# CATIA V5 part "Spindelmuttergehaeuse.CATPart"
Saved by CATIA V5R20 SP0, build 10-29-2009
Part number: Spindelmuttergehäuse
Bounding box of the stored display mesh (mm): x -38 to 25, y -20 to 20, z 0 to 32
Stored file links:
  C:\Users\Andi\Desktop\Offene Projekte\Plasmacutter\Portal\Spindelmuttergehaeuse.CATPart
  C:\Program Files\Dassault Systemes\B20\win_b64\reffiles\standard\MetricThickPitch.txt
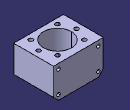
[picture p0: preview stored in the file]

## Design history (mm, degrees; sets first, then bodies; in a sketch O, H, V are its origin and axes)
Body1 (main body)
  Sketch1 on xy-plane, origin (0, 0, 0), H (1, 0, 0), V (0, 1, 0)
    point P1 (0, 0)
    line L1 (25, 20) -> (25, -20)
    line L2 (25, -20) -> (-25, -20)
    line L3 (-25, -20) -> (-25, 20)
    line L4 (-25, 20) -> (25, 20)
    circle A1 centre (0, -1) radius 14
    point P6 (0, -1)
    distance L2 L4 = 40
    distance L1 L3 = 50
    radius A1 = 14
    distance P6 L4 = 21
    coincidence: P1 V, P1 O, P6 V
    vertical: L1 V, L3 V
    horizontal: L2 H, L4 H
    equidistance: L1 L3 P1, L2 L4 P1
  Pad1: profile Sketch1, direction (0, 0, 1), length 32
  Sketch2 on end face of Pad1, origin (-15.5839, 12.1937, 32), H (1, 0, 0), V (0, 1, 0)
    point P1 (-3.4161, -13.1937)
    reference intersected line E1 through (15.5839, 0) direction (0, 1) from yz-plane
    construction line L1 (15.5839, -13.1937) -> (26.0291, -13.1937)
    point P2 (15.5839, -13.1937)
    reference projected circle E2 centre (15.5839, -13.1937) radius 14 from edge [end face of Pad1 | face of Pad1 from Sketch1.A1]
    distance E1 P1 = 19
    horizontal: L1 H
    concentricity: P2 E2
    coincidence: P1 L1
  Hole1: placed by Sketch2, at (-19, -1, 32) direction (0, 0, -1), diameter 4.134, depth 15, V-bottom angle 120, threaded "M5", thread diameter 5, thread depth 12, pitch 0.8
  CircPattern1: of Hole1, instances 8, angular step 45, axis from face of Pad1 from Sketch1.A1
  Sketch3 on face of Pad1 from Sketch1.L4, origin (-21.5351, 20, 4.2073), H (1, 0, 0), V (0, 0, -1)
    point P1 (1.5351, -0.7927)
    reference projected line E1 (46.5351, 4.2073) -> (-3.4649, 4.2073) from edge [start face of Pad1 | face of Pad1 from Sketch1.L4]
    reference intersected line E2 through (21.5351, 0) direction (0, 1) from yz-plane
    distance E1 P1 = 5
    distance E2 P1 = 20
  Hole2: placed by Sketch3, at (-20, 20, 5) direction (0, -1, 0), diameter 3.242, depth 12, V-bottom angle 120, threaded "M4", thread diameter 4, thread depth 8, pitch 0.7
  RectPattern1: of Hole2, direction 1 instances 2, spacing 40, along face of Pad1 from Sketch1.L4, direction 2 instances 2, spacing 22, along face of Pad1 from Sketch1.L4 reversed
  Chamfer1: length 5, angle 45, on edge [start face of Pad1 | face of Pad1 from Sketch1.L3]; edge [start face of Pad1 | face of Pad1 from Sketch1.L1]
  Sketch4 on face of Pad1 from Sketch1.L2, origin (0, -20, 0), H (1, 0, 0), V (0, 0, 1)
    projected line E1 (-20, 0) -> (-25, 5) from edge [face of Pad1 from Sketch1.L2 | face of Chamfer1]
    point P2 (-25, 5)
    projected line E2 (-25, 5) -> (-25, 32) from edge [face of Pad1 from Sketch1.L2 | face of Pad1 from Sketch1.L3]
    projected line E3 (-25, 5) -> (-25, 15) from edge [face of Pad1 from Sketch1.L2 | face of Pad1 from Sketch1.L3]
    point P3 (-25, 5)
    line L1 (-20, 0) -> (-38, 0)
    line L2 (-38, 0) -> (-38, 15)
    line L3 (-38, 15) -> (-25, 15)
    distance L2 E2 = 13
    distance L3 L1 = 15
    horizontal: L1 H, L3 H
    vertical: L2 V
    coincidence: P2 P3
  Pad2: profile Sketch4, direction (0, 1, 0), length 19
